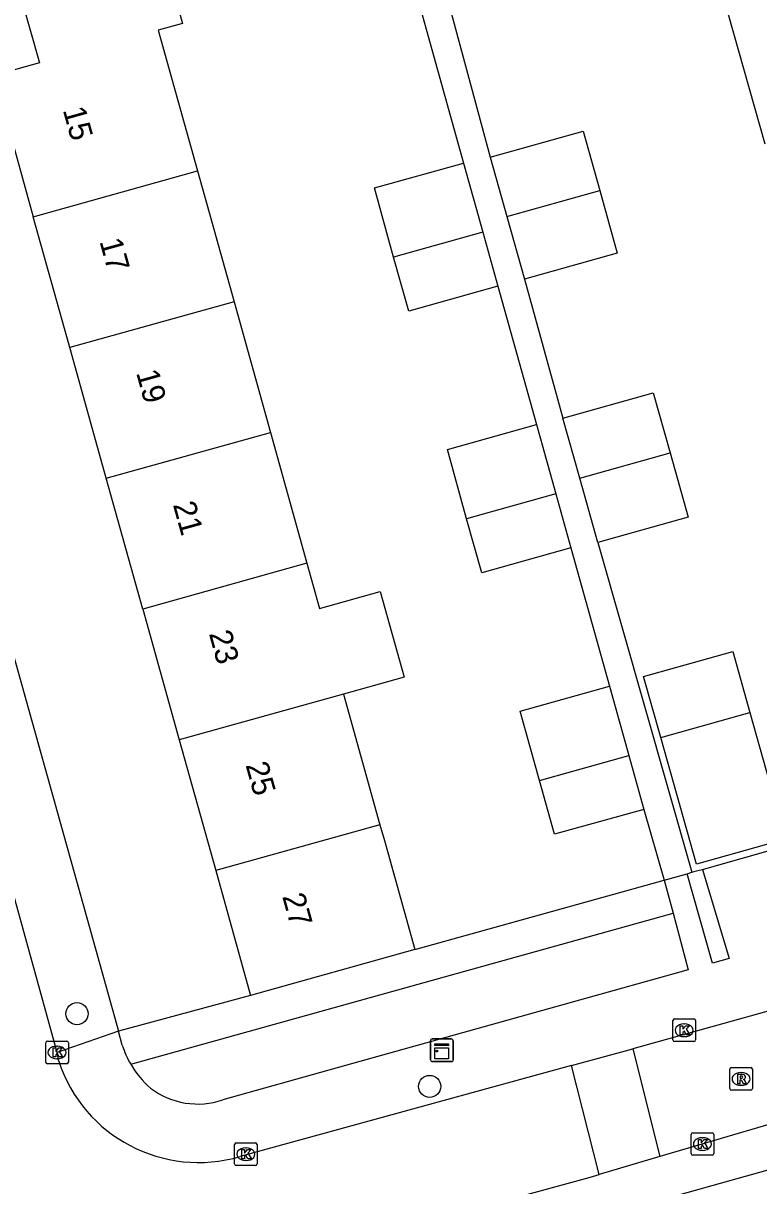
# Model space of a CAD drawing. Extents: x 159053 to 160041, y 380450 to 381422.
# Drawn here: x 159177.2 to 159209.7, y 380913.3 to 380964.7 of the extents above; entities that cross this region are included whole.
import ezdxf

# ---------------------------------------------------------------- set-up
doc = ezdxf.new("R2010")
doc.units = 0
for name, color, linetype in [('IMGEO_Boom', 7, 'Continuous'), ('IMGEO_Groenvoorziening', 7, 'Continuous'), ('IMGEO_Haag', 7, 'Continuous'), ('IMGEO_Kast', 7, 'Continuous'), ('IMGEO_Kolk', 7, 'Continuous'), ('IMGEO_Pand', 7, 'Continuous'), ('IMGEO_Pand_nummerreeks', 7, 'Continuous'), ('IMGEO_Rijbaan_lokaal_open', 7, 'Continuous'), ('IMGEO_Rioolput', 7, 'Continuous'), ('IMGEO_Voetpad_open', 7, 'Continuous')]:
    doc.layers.add(name, color=color, linetype=linetype)

msp = doc.modelspace()

# ---------------------------------------------------------------- linework, layer by layer
at = {"layer": 'IMGEO_Boom'}
for centre in [(159179.563, 380920.925), (159195.142, 380917.713)]:
    msp.add_circle(centre, 0.489, dxfattribs=at)
at = {"layer": 'IMGEO_Groenvoorziening'}
for points in [[(159194.484, 380923.76), (159205.498, 380926.825)], [(159181.941, 380918.69), (159205.89, 380925.371)], [(159187.228, 380921.737), (159181.394, 380920.15)]]:
    msp.add_lwpolyline(points, dxfattribs=at)
at = {"layer": 'IMGEO_Haag'}
msp.add_lwpolyline([(159206.725, 380927.174), (159206.931, 380927.233), (159207.189, 380927.306)], dxfattribs=at)
at = {"layer": 'IMGEO_Kast'}
for p, q in [((159195.179, 380918.884), (159195.179, 380919.725)), ((159195.179, 380919.725), (159195.179, 380918.884)), ((159195.254, 380919.809), (159196.095, 380919.809)), ((159196.095, 380919.809), (159195.254, 380919.809)), ((159196.179, 380919.734), (159196.179, 380918.893)), ((159196.179, 380918.893), (159196.179, 380919.734)), ((159196.104, 380918.809), (159195.263, 380918.809)), ((159195.263, 380918.809), (159196.104, 380918.809))]:
    msp.add_line(p, q, dxfattribs=at)
for points in [[(159195.374, 380919.599), (159195.974, 380919.599), (159195.974, 380919.514), (159195.374, 380919.514), (159195.374, 380919.599)], [(159195.374, 380919.424), (159195.974, 380919.424), (159195.974, 380918.935), (159195.374, 380918.935), (159195.374, 380919.424)]]:
    msp.add_lwpolyline(points, dxfattribs=at)
msp.add_circle((159195.458, 380919.273), 0.0377, dxfattribs=at)
for centre, start, end in [((159195.257, 380919.731), 92.4484, 184.2845), ((159195.257, 380919.731), 92.4484, 184.2845), ((159196.101, 380919.731), 2.4484, 94.2845), ((159196.101, 380919.731), 2.4484, 94.2845), ((159195.257, 380918.887), 182.4484, 274.2845), ((159195.257, 380918.887), 182.4484, 274.2845), ((159196.101, 380918.887), 272.4484, 4.2845), ((159196.101, 380918.887), 272.4484, 4.2845)]:
    msp.add_arc(centre, 0.0779, start, end, dxfattribs=at)
at = {"layer": 'IMGEO_Kolk'}
for p, q in [((159205.883, 380919.769), (159205.883, 380920.621)), ((159205.958, 380920.695), (159206.81, 380920.695)), ((159206.371, 380920.475), (159206.396, 380920.475)), ((159206.884, 380920.621), (159206.884, 380919.769)), ((159206.394, 380919.915), (159206.369, 380919.915)), ((159178.185, 380918.787), (159178.185, 380919.639)), ((159178.26, 380919.713), (159179.112, 380919.713)), ((159178.673, 380919.493), (159178.698, 380919.493)), ((159179.186, 380919.639), (159179.186, 380918.787)), ((159206.81, 380919.695), (159205.958, 380919.695)), ((159178.696, 380918.933), (159178.671, 380918.933)), ((159179.112, 380918.713), (159178.26, 380918.713)), ((159206.689, 380914.742), (159206.689, 380915.594)), ((159206.764, 380915.668), (159207.616, 380915.668)), ((159207.177, 380915.448), (159207.202, 380915.448)), ((159207.69, 380915.594), (159207.69, 380914.742)), ((159186.522, 380914.292), (159186.522, 380915.144)), ((159186.597, 380915.218), (159187.449, 380915.218)), ((159187.01, 380914.998), (159187.035, 380914.998)), ((159187.523, 380915.144), (159187.523, 380914.292)), ((159207.2, 380914.888), (159207.175, 380914.888)), ((159187.449, 380914.218), (159186.597, 380914.218)), ((159187.033, 380914.438), (159187.008, 380914.438)), ((159207.616, 380914.668), (159206.764, 380914.668))]:
    msp.add_line(p, q, dxfattribs=at)
for points in [[(159205.883, 380919.769), (159205.883, 380920.621)], [(159205.958, 380920.695), (159206.81, 380920.695)], [(159206.204, 380920.395), (159206.327, 380920.395), (159206.327, 380920.244), (159206.457, 380920.395), (159206.621, 380920.395), (159206.475, 380920.244), (159206.628, 380919.995), (159206.476, 380919.995), (159206.391, 380920.159), (159206.327, 380920.092), (159206.327, 380919.995), (159206.204, 380919.995), (159206.204, 380920.395)], [(159206.884, 380920.621), (159206.884, 380919.769)], [(159178.185, 380918.787), (159178.185, 380919.639)], [(159178.26, 380919.713), (159179.112, 380919.713)], [(159178.506, 380919.413), (159178.629, 380919.413), (159178.629, 380919.262), (159178.759, 380919.413), (159178.923, 380919.413), (159178.777, 380919.262), (159178.93, 380919.013), (159178.778, 380919.013), (159178.693, 380919.177), (159178.629, 380919.11), (159178.629, 380919.013), (159178.506, 380919.013), (159178.506, 380919.413)], [(159179.186, 380919.639), (159179.186, 380918.787)], [(159206.81, 380919.695), (159205.958, 380919.695)], [(159179.112, 380918.713), (159178.26, 380918.713)], [(159206.689, 380914.742), (159206.689, 380915.594)], [(159206.764, 380915.668), (159207.616, 380915.668)], [(159207.01, 380915.368), (159207.133, 380915.368), (159207.133, 380915.217), (159207.263, 380915.368), (159207.427, 380915.368), (159207.281, 380915.217), (159207.434, 380914.968), (159207.282, 380914.968), (159207.197, 380915.132), (159207.133, 380915.065), (159207.133, 380914.968), (159207.01, 380914.968), (159207.01, 380915.368)], [(159207.69, 380915.594), (159207.69, 380914.742)], [(159186.522, 380914.292), (159186.522, 380915.144)], [(159186.597, 380915.218), (159187.449, 380915.218)], [(159186.843, 380914.918), (159186.966, 380914.918), (159186.966, 380914.767), (159187.096, 380914.918), (159187.26, 380914.918), (159187.114, 380914.767), (159187.267, 380914.518), (159187.115, 380914.518), (159187.03, 380914.682), (159186.966, 380914.615), (159186.966, 380914.518), (159186.843, 380914.518), (159186.843, 380914.918)], [(159187.523, 380915.144), (159187.523, 380914.292)], [(159187.449, 380914.218), (159186.597, 380914.218)], [(159207.616, 380914.668), (159206.764, 380914.668)]]:
    msp.add_lwpolyline(points, dxfattribs=at)
for centre, start, end in [((159205.96, 380920.619), 91.552, 178.448), ((159205.96, 380920.619), 91.552, 178.448), ((159206.808, 380920.619), 1.552, 88.448), ((159206.808, 380920.619), 1.552, 88.448), ((159178.262, 380919.637), 91.552, 178.448), ((159178.262, 380919.637), 91.552, 178.448), ((159179.11, 380919.637), 1.552, 88.448), ((159179.11, 380919.637), 1.552, 88.448), ((159205.96, 380919.771), 181.552, 268.448), ((159205.96, 380919.771), 181.552, 268.448), ((159206.808, 380919.771), 271.552, 358.448), ((159206.808, 380919.771), 271.552, 358.448), ((159178.262, 380918.789), 181.552, 268.448), ((159178.262, 380918.789), 181.552, 268.448), ((159179.11, 380918.789), 271.552, 358.448), ((159179.11, 380918.789), 271.552, 358.448), ((159206.766, 380915.592), 91.552, 178.448), ((159206.766, 380915.592), 91.552, 178.448), ((159207.614, 380915.592), 1.552, 88.448), ((159207.614, 380915.592), 1.552, 88.448), ((159186.599, 380915.142), 91.552, 178.448), ((159186.599, 380915.142), 91.552, 178.448), ((159187.447, 380915.142), 1.552, 88.448), ((159187.447, 380915.142), 1.552, 88.448), ((159206.766, 380914.744), 181.552, 268.448), ((159206.766, 380914.744), 181.552, 268.448), ((159207.614, 380914.744), 271.552, 358.448), ((159207.614, 380914.744), 271.552, 358.448), ((159186.599, 380914.294), 181.552, 268.448), ((159186.599, 380914.294), 181.552, 268.448), ((159187.447, 380914.294), 271.552, 358.448), ((159187.447, 380914.294), 271.552, 358.448)]:
    msp.add_arc(centre, 0.0765, start, end, dxfattribs=at)
for centre, major_axis, ratio, start_param, end_param in [((159206.37, 380920.195), (-0.387, 0.002), 0.722429, 4.712389, 7.853982), ((159206.395, 380920.195), (-0.39, 0.002), 0.717154, 1.570796, 4.712389), ((159178.672, 380919.213), (-0.387, 0.002), 0.722429, 4.712389, 7.853982), ((159178.697, 380919.213), (-0.39, 0.002), 0.717154, 1.570796, 4.712389), ((159207.176, 380915.168), (-0.387, 0.002), 0.722429, 4.712389, 7.853982), ((159207.201, 380915.168), (-0.39, 0.002), 0.717154, 1.570796, 4.712389), ((159187.009, 380914.718), (-0.387, 0.002), 0.722429, 4.712389, 7.853982), ((159187.034, 380914.718), (-0.39, 0.002), 0.717154, 1.570796, 4.712389)]:
    msp.add_ellipse(centre, major_axis=major_axis, ratio=ratio, start_param=start_param, end_param=end_param, dxfattribs=at)
at = {"layer": 'IMGEO_Pand'}
for points in [[(159183.402, 380967.628), (159184.22, 380964.692), (159183.154, 380964.397), (159184.89, 380958.171)], [(159177.091, 380965.868), (159177.907, 380962.943), (159175.895, 380962.386), (159177.634, 380956.147)], [(159209.955, 380959.35), (159208.333, 380965.127)], [(159197.819, 380958.771), (159201.916, 380959.921), (159202.651, 380957.3)], [(159193.552, 380954.359), (159192.7, 380957.417), (159196.643, 380958.516)], [(159196.643, 380958.516), (159197.495, 380955.459)], [(159197.819, 380958.771), (159198.554, 380956.15)], [(159177.634, 380956.147), (159184.89, 380958.171)], [(159184.89, 380958.171), (159186.501, 380952.392)], [(159198.554, 380956.15), (159202.651, 380957.3)], [(159202.651, 380957.3), (159203.425, 380954.542), (159199.328, 380953.392)], [(159179.246, 380950.368), (159177.634, 380956.147)], [(159198.554, 380956.15), (159199.328, 380953.392)], [(159197.495, 380955.459), (159193.552, 380954.359)], [(159197.495, 380955.459), (159198.16, 380953.074)], [(159198.16, 380953.074), (159194.217, 380951.974), (159193.552, 380954.359)], [(159186.501, 380952.392), (159179.246, 380950.368)], [(159186.501, 380952.392), (159188.113, 380946.612)], [(159180.857, 380944.589), (159179.246, 380950.368)], [(159201.029, 380947.242), (159205.017, 380948.362), (159205.762, 380945.71)], [(159201.773, 380944.591), (159201.029, 380947.242)], [(159180.857, 380944.589), (159188.113, 380946.612)], [(159188.113, 380946.612), (159189.724, 380940.833)], [(159196.775, 380942.8), (159195.923, 380945.858), (159199.866, 380946.957)], [(159199.866, 380946.957), (159200.718, 380943.9)], [(159201.773, 380944.591), (159205.762, 380945.71)], [(159205.762, 380945.71), (159206.559, 380942.871), (159202.571, 380941.751)], [(159182.468, 380938.809), (159180.857, 380944.589)], [(159202.571, 380941.751), (159201.773, 380944.591)], [(159200.718, 380943.9), (159196.775, 380942.8)], [(159200.718, 380943.9), (159201.383, 380941.515)], [(159201.383, 380941.515), (159197.44, 380940.415), (159196.775, 380942.8)], [(159189.724, 380940.833), (159182.468, 380938.809)], [(159189.724, 380940.833), (159190.281, 380938.835), (159192.959, 380939.582), (159194.014, 380935.8), (159191.335, 380935.053)], [(159182.468, 380938.809), (159184.08, 380933.03)], [(159205.35, 380933.131), (159204.594, 380935.825), (159208.526, 380936.929), (159209.282, 380934.235)], [(159199.999, 380931.239), (159199.146, 380934.298), (159203.089, 380935.397)], [(159203.089, 380935.397), (159203.942, 380932.338)], [(159191.335, 380935.053), (159184.08, 380933.03)], [(159191.335, 380935.053), (159192.947, 380929.273)], [(159209.282, 380934.235), (159210.854, 380928.637), (159206.922, 380927.533), (159205.35, 380933.131)], [(159205.35, 380933.131), (159209.282, 380934.235)], [(159184.08, 380933.03), (159185.691, 380927.25)], [(159199.999, 380931.239), (159203.942, 380932.338)], [(159203.942, 380932.338), (159204.606, 380929.955)], [(159204.606, 380929.955), (159200.663, 380928.855), (159199.999, 380931.239)], [(159192.947, 380929.273), (159185.691, 380927.25)], [(159192.947, 380929.273), (159193.141, 380928.577), (159194.484, 380923.76)], [(159185.691, 380927.25), (159187.228, 380921.737)], [(159194.484, 380923.76), (159187.228, 380921.737)]]:
    msp.add_lwpolyline(points, dxfattribs=at)
at = {"layer": 'IMGEO_Rijbaan_lokaal_open'}
for points in [[(159178.686, 380919.213), (159173.619, 380937.536), (159168.82, 380954.965), (159167.736, 380958.963)], [(159270.392, 380932.872), (159251.048, 380927.477), (159212.83, 380916.824), (159205.315, 380914.615)], [(159228.811, 380926.254), (159204.121, 380919.367)], [(159201.414, 380918.639), (159204.121, 380919.367)], [(159204.121, 380919.367), (159205.315, 380914.615)], [(159178.764, 380918.825), (159178.686, 380919.213)], [(159201.414, 380918.639), (159186.773, 380914.618)], [(159202.625, 380913.824), (159201.414, 380918.639)], [(159205.315, 380914.615), (159202.625, 380913.824)], [(159183.081, 380908.43), (159183.581, 380908.568), (159191.928, 380910.886), (159193.225, 380911.241), (159202.183, 380913.694), (159202.625, 380913.824)]]:
    msp.add_lwpolyline(points, dxfattribs=at)
msp.add_arc((159184.934, 380920.845), 6.492, 198.1243, 286.4513, dxfattribs=at)
at = {"layer": 'IMGEO_Rioolput'}
for p, q in [((159208.397, 380917.616), (159208.397, 380918.468)), ((159208.472, 380918.542), (159209.324, 380918.542)), ((159208.885, 380918.322), (159208.91, 380918.322)), ((159209.398, 380918.468), (159209.398, 380917.616)), ((159209.324, 380917.542), (159208.472, 380917.542)), ((159208.908, 380917.762), (159208.883, 380917.762))]:
    msp.add_line(p, q, dxfattribs=at)
for points in [[(159208.397, 380917.616), (159208.397, 380918.468)], [(159208.472, 380918.542), (159209.324, 380918.542)], [(159209.398, 380918.468), (159209.398, 380917.616)], [(159208.986, 380918.24), (159208.734, 380918.242), (159208.734, 380917.842)], [(159208.734, 380917.842), (159208.858, 380917.842), (159208.858, 380918.004), (159208.869, 380918.004)], [(159208.912, 380918.161), (159208.858, 380918.161), (159208.858, 380918.08)], [(159208.858, 380918.08), (159208.91, 380918.08)], [(159208.916, 380917.975), (159208.987, 380917.842), (159209.127, 380917.842), (159209.062, 380917.968)], [(159209.324, 380917.542), (159208.472, 380917.542)]]:
    msp.add_lwpolyline(points, dxfattribs=at)
for centre, radius, start, end in [((159208.474, 380918.466), 0.0765, 91.552, 178.448), ((159208.474, 380918.466), 0.0765, 91.552, 178.448), ((159209.322, 380918.466), 0.0765, 1.552, 88.448), ((159209.322, 380918.466), 0.0765, 1.552, 88.448), ((159208.868, 380917.951), 0.0533, 26.0293, 88.6989), ((159208.894, 380918.269), 0.19, 274.7715, 282.9687), ((159208.918, 380918.065), 0.0964, 77.0061, 93.1865), ((159208.932, 380918.122), 0.0378, 276.6634, 79.6772), ((159208.985, 380918.13), 0.109, 350.3612, 89.416), ((159208.983, 380918.13), 0.112, 277.5842, 350.9817), ((159208.967, 380917.915), 0.108, 29.5134, 73.7905), ((159208.474, 380917.618), 0.0765, 181.552, 268.448), ((159208.474, 380917.618), 0.0765, 181.552, 268.448), ((159209.322, 380917.618), 0.0765, 271.552, 358.448), ((159209.322, 380917.618), 0.0765, 271.552, 358.448)]:
    msp.add_arc(centre, radius, start, end, dxfattribs=at)
for centre, major_axis, ratio, start_param, end_param in [((159208.884, 380918.042), (-0.387, 0.002), 0.722429, 4.712389, 7.853982), ((159208.909, 380918.042), (-0.39, 0.002), 0.717154, 1.570796, 4.712389)]:
    msp.add_ellipse(centre, major_axis=major_axis, ratio=ratio, start_param=start_param, end_param=end_param, dxfattribs=at)
at = {"layer": 'IMGEO_Voetpad_open'}
for points in [[(159156.992, 381007.402), (159159.094, 381000), (159181.394, 380920.15)], [(159194.097, 380967.675), (159196.643, 380958.516)], [(159195.335, 380967.948), (159197.819, 380958.771)], [(159199.328, 380953.392), (159201.029, 380947.242)], [(159198.16, 380953.074), (159199.866, 380946.957)], [(159201.383, 380941.515), (159203.089, 380935.397)], [(159202.571, 380941.751), (159206.725, 380927.174)], [(159194.248, 380908.271), (159195.395, 380909.913), (159199.726, 380911.13), (159295.42, 380937.918), (159296.393, 380934.435), (159296.42, 380934.314)], [(159204.606, 380929.955), (159205.498, 380926.825)], [(159207.189, 380927.306), (159212.208, 380928.733)], [(159205.498, 380926.825), (159206.511, 380927.113)], [(159207.189, 380927.306), (159208.373, 380923.373), (159207.997, 380923.268), (159207.633, 380923.166), (159206.511, 380927.113)], [(159206.511, 380927.113), (159206.725, 380927.174)], [(159205.498, 380926.825), (159205.89, 380925.371)], [(159205.89, 380925.371), (159206.564, 380922.867), (159191.052, 380918.531), (159186.01, 380917.122)], [(159181.394, 380920.15), (159178.686, 380919.213)], [(159181.566, 380919.535), (159181.394, 380920.15)]]:
    msp.add_lwpolyline(points, dxfattribs=at)
for centre, radius, start, end in [((159185.535, 380920.791), 4.163, 197.5567, 210.3053), ((159185.552, 380920.801), 4.183, 210.3105, 229.129), ((159184.893, 380920.354), 3.419, 232.5807, 289.071)]:
    msp.add_arc(centre, radius, start, end, dxfattribs=at)

# ---------------------------------------------------------------- texts
at = {"layer": 'IMGEO_Pand_nummerreeks'}
for s, p in [('15', (159178.934, 380960.867)), ('17', (159180.553, 380955.06)), ('19', (159182.172, 380949.253)), ('21', (159183.797, 380943.425)), ('23', (159185.386, 380937.727)), ('25', (159187.005, 380931.92)), ('27', (159188.624, 380926.113))]:
    msp.add_text(s, height=1, rotation=285.5785, dxfattribs=at).set_placement(p)

doc.saveas('drawing.dxf')
